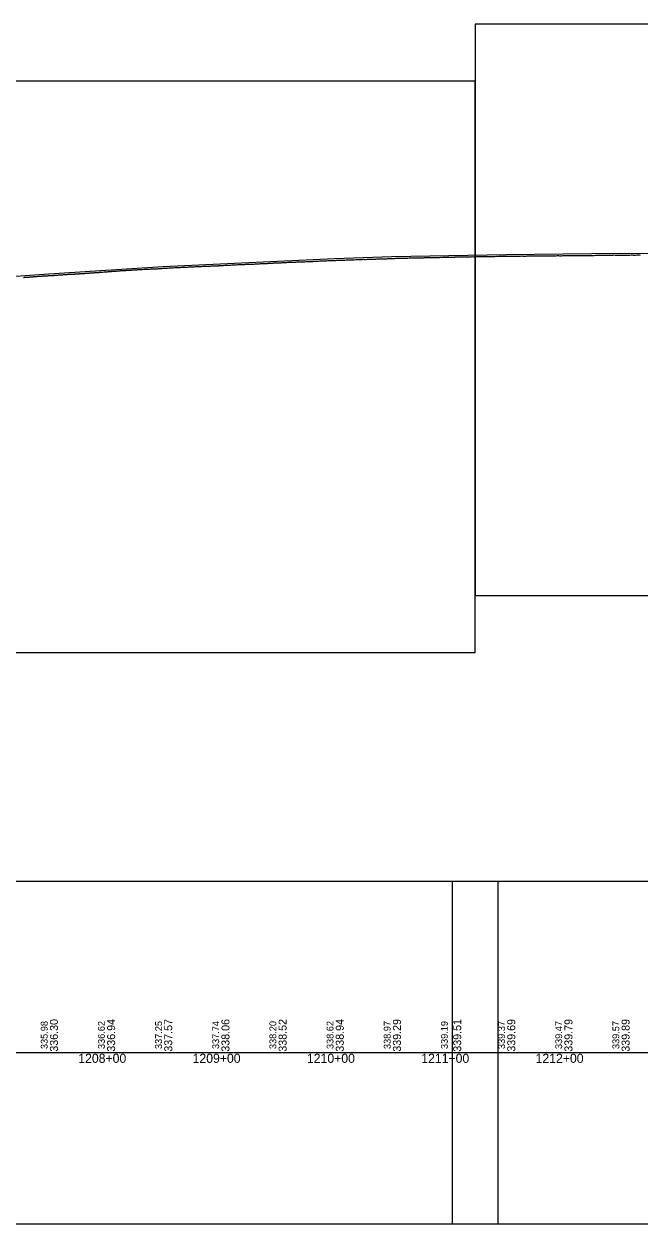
# Model space of a CAD drawing. Extents: x -3627 to 47473, y 2850 to 4350.
# Drawn here: x 8106 to 8644, y 2850 to 3900 of the extents above; entities that cross this region are included whole.
import ezdxf

# ---------------------------------------------------------------- set-up
doc = ezdxf.new("R2010")
doc.units = 0
for name, color, linetype in [('RD_DDB_Profile_EX', 7, 'Continuous'), ('RD_DDB_Profile_PR', 7, 'Continuous'), ('RD_DDB_StaTX', 7, 'Continuous'), ('RD_DDB_StripGrade', 7, 'Continuous'), ('RD_GPK_Profile_Cell', 7, 'Continuous'), ('RD_SHT_ShtClip', 7, 'Continuous')]:
    doc.layers.add(name, color=color, linetype=linetype)

msp = doc.modelspace()

# ---------------------------------------------------------------- linework, layer by layer
at = {"layer": 'RD_DDB_Profile_EX'}
for points in [[(8468.94793, 3695.81724), (8469.943036, 3695.866545), (8470.591115, 3695.818705), (8471.584155, 3695.87025), (8472.576556, 3695.86732), (8473.579379, 3695.86649), (8474.57258, 3695.865875), (8475.575565, 3695.91508), (8476.578407, 3695.96363), (8477.571559, 3695.96294), (8478.572907, 3695.958895), (8479.575681, 3695.95811), (8480.578538, 3696.006895), (8481.571496, 3696.05564), (8482.12012, 3696.109715), (8482.574301, 3696.153895), (8483.577047, 3696.15262), (8484.568784, 3696.14851), (8485.662579, 3696.14695), (8486.911776, 3696.144415), (8487.659355, 3696.14225), (8488.66334, 3696.24287), (8489.656766, 3696.24039), (8490.660179, 3696.237365), (8491.703432, 3696.23449), (8492.657639, 3696.23483), (8493.661105, 3696.281105), (8494.664573, 3696.277845), (8495.65805, 3696.324055), (8496.662094, 3696.37366), (8497.665618, 3696.419805), (8498.65915, 3696.36635), (8499.185064, 3696.363645), (8500.189303, 3696.41581), (8501.286743, 3696.469145), (8502.188107, 3696.47203), (8503.182525, 3696.47508), (8504.186972, 3696.477495), (8505.181283, 3696.47692), (8506.182221, 3696.52899), (8507.177132, 3696.58141), (8508.182012, 3696.583425), (8509.176921, 3696.585565), (8510.181801, 3696.5872), (8510.870055, 3696.5541), (8511.176718, 3696.5393), (8512.180877, 3696.58685), (8513.175815, 3696.58855), (8513.52939, 3696.590835), (8514.533886, 3696.63829), (8515.66171, 3696.639695), (8516.533417, 3696.64066), (8517.538063, 3696.68764), (8518.532887, 3696.73861), (8519.537498, 3696.685875), (8520.532367, 3696.73663), (8521.537316, 3696.7865), (8522.532096, 3696.73352), (8523.537038, 3696.783565), (8524.53203, 3696.83394), (8525.536799, 3696.83029), (8526.531932, 3696.83034), (8527.536785, 3696.82633), (8528.526075, 3696.875835), (8529.011668, 3696.926), (8530.036677, 3696.929565), (8531.012454, 3696.92819), (8532.008196, 3696.93118), (8533.013885, 3696.98334), (8534.009664, 3696.98626), (8535.005419, 3696.939025), (8536.01122, 3696.94089), (8537.007031, 3696.9929), (8538.01222, 3696.991185), (8539.008031, 3696.94339), (8539.619989, 3696.97541), (8540.003882, 3696.99521), (8541.009747, 3697.046345), (8542.005637, 3696.99797), (8543.011508, 3696.999115), (8543.57207, 3696.971855), (8544.411644, 3696.977315), (8544.731209, 3696.9982), (8545.727102, 3697.049125), (8546.723014, 3697.00005), (8547.729062, 3697.000435), (8548.72518, 3697.051065), (8549.2033, 3697.05125), (8549.731208, 3697.05126), (8550.727323, 3697.05159), (8551.402762, 3697.08361), (8551.732185, 3697.098915), (8552.728465, 3697.099285), (8553.994956, 3697.099665), (8554.730595, 3697.099275), (8555.7265, 3697.14909), (8556.732892, 3697.19852), (8557.727472, 3697.194955), (8558.786612, 3697.094875), (8559.729585, 3697.09385), (8560.727446, 3697.14313)], [(8560.727446, 3697.14313), (8561.731695, 3697.14204), (8562.730001, 3697.141325), (8563.726318, 3697.19053), (8564.882987, 3697.236155), (8565.889759, 3697.237695), (8566.886999, 3697.19329), (8567.883786, 3697.14543), (8568.369923, 3697.170815), (8568.880633, 3697.197195), (8569.514814, 3697.2), (8569.888699, 3697.20125), (8570.88626, 3697.252285), (8571.883832, 3697.303385), (8573.161579, 3697.29368), (8573.890559, 3697.25784), (8574.888014, 3697.258995), (8575.887442, 3697.26245), (8576.884935, 3697.312675), (8577.953234, 3697.36365), (8578.891382, 3697.366865), (8579.88874, 3697.36644), (8580.886129, 3697.415225), (8582.132423, 3697.41787), (8582.74489, 3697.38733), (8583.148776, 3697.37099), (8584.159097, 3697.373285), (8585.157466, 3697.425795), (8586.157831, 3697.42692), (8587.158515, 3697.37924), (8587.536546, 3697.39906), (8588.158688, 3697.43128), (8589.155629, 3697.43064), (8590.164898, 3697.480585), (8591.165186, 3697.43717), (8592.328201, 3697.47965), (8593.164677, 3697.440655), (8594.164592, 3697.442135), (8595.160884, 3697.535645), (8596.424402, 3697.54016), (8597.420888, 3697.54086), (8598.417556, 3697.54113), (8599.423269, 3697.49094), (8600.419515, 3697.48922), (8601.418806, 3697.53692), (8601.911513, 3697.560955), (8602.415023, 3697.582025), (8603.420781, 3697.53144), (8604.416901, 3697.531065), (8605.413289, 3697.587145), (8606.703168, 3697.595745), (8607.417437, 3697.62848), (8608.41359, 3697.674985), (8609.409513, 3697.720675), (8610.415135, 3697.67015), (8611.494824, 3697.721955), (8612.405101, 3697.76615), (8613.620711, 3697.76436), (8614.621041, 3697.765485), (8615.621393, 3697.76784), (8616.28648, 3697.7694), (8616.621714, 3697.77005), (8617.621971, 3697.81899), (8618.622188, 3697.869535), (8619.622443, 3697.824635), (8620.622697, 3697.829005), (8621.078136, 3697.85269), (8621.622852, 3697.879385), (8622.623012, 3697.83512), (8623.623173, 3697.83832), (8624.623333, 3697.83857), (8625.869791, 3697.799695), (8626.623853, 3697.83824), (8627.625756, 3697.847325), (8628.625764, 3697.846655), (8629.625841, 3697.84599), (8630.661447, 3697.845265), (8631.625912, 3697.841965), (8632.576806, 3697.843835), (8633.576828, 3697.802625), (8634.576849, 3697.851385), (8635.578675, 3697.852455), (8636.578593, 3697.898365), (8637.578512, 3697.898645), (8638.57843, 3697.8556), (8639.580145, 3697.85842), (8640.58003, 3697.8539), (8641.579851, 3697.901435), (8642.60486, 3697.951475), (8643.607934, 3697.903895), (8644.607849, 3697.85144)], [(8189.829123, 3684.147975), (8190.292238, 3684.19276), (8190.595755, 3684.17839), (8191.293806, 3684.246265), (8191.595796, 3684.2616), (8192.588766, 3684.293895), (8193.588782, 3684.336805), (8194.620779, 3684.42178), (8195.588801, 3684.46876), (8196.588704, 3684.54406), (8197.588676, 3684.605875), (8198.588646, 3684.661095), (8199.588564, 3684.744165), (8200.588495, 3684.778115), (8201.588424, 3684.812385), (8202.588351, 3684.88705), (8203.308945, 3684.948635), (8204.307813, 3684.9965), (8205.307013, 3685.06899), (8206.305388, 3685.116405), (8207.296257, 3685.176375), (8208.295701, 3685.212865), (8209.293926, 3685.2978), (8210.348583, 3685.39595), (8211.345577, 3685.39319), (8212.343902, 3685.377045), (8213.340846, 3685.446675), (8213.787402, 3685.467815), (8214.338974, 3685.482805), (8215.335555, 3685.567475), (8216.333514, 3685.643115), (8217.329646, 3685.649995), (8218.579057, 3685.809255), (8219.323814, 3685.854045), (8220.321399, 3685.82103), (8221.31749, 3685.85768), (8222.313538, 3685.878465), (8223.370713, 3686.052105), (8224.301282, 3686.10602), (8225.301519, 3686.15631), (8226.300221, 3686.19556), (8227.298924, 3686.25301), (8228.299123, 3686.267195), (8229.297517, 3686.297845), (8230.29591, 3686.40795), (8231.295847, 3686.490325), (8232.293923, 3686.52077), (8233.293761, 3686.553375), (8234.291859, 3686.668615), (8235.289958, 3686.67496), (8236.178328, 3686.75826), (8237.178328, 3686.797955), (8238.178329, 3686.84614), (8239.178331, 3686.90324), (8240.56958, 3687.008155), (8241.568906, 3687.06518), (8242.568227, 3687.0721), (8243.566948, 3687.12067), (8244.567617, 3687.16382), (8245.566355, 3687.1625), (8246.565392, 3687.21149), (8247.56436, 3687.303045), (8248.562822, 3687.351535), (8249.561571, 3687.400305), (8250.561677, 3687.450395), (8251.560442, 3687.470435), (8252.558822, 3687.5185), (8253.557306, 3687.566685), (8254.555799, 3687.65136), (8255.421101, 3687.69353), (8255.970195, 3687.698965), (8256.970244, 3687.755645), (8257.970129, 3687.80514), (8258.969568, 3687.877365), (8259.96946, 3687.88342), (8260.969431, 3687.89605), (8261.990175, 3687.98782), (8262.990337, 3688.075435), (8263.990629, 3688.03842), (8264.989889, 3688.043285), (8265.990181, 3688.087475), (8266.495614, 3688.138), (8266.990268, 3688.18127), (8267.989361, 3688.18585), (8268.770621, 3688.192605), (8269.770589, 3688.292485), (8270.770767, 3688.38026), (8271.28727, 3688.38097), (8271.772104, 3688.400305), (8272.771812, 3688.43736), (8273.771732, 3688.474725), (8274.771436, 3688.524375), (8275.772649, 3688.531675), (8276.078926, 3688.546815), (8276.772388, 3688.60008), (8277.771826, 3688.73685), (8278.771475, 3688.78019), (8279.271242, 3688.780395), (8280.271472, 3688.793725), (8281.271697, 3688.844555), (8282.354178, 3688.893675)], [(8282.354178, 3688.893675), (8283.354956, 3688.9006), (8284.355735, 3688.90761), (8285.356513, 3688.945585), (8285.662237, 3688.976095), (8286.346628, 3689.025425), (8287.34711, 3689.13198), (8288.347337, 3689.238335), (8289.347818, 3689.244955), (8290.453893, 3689.298915), (8291.346743, 3689.349765), (8292.346922, 3689.44974), (8293.347101, 3689.449715), (8294.345503, 3689.44782), (8295.345652, 3689.54165), (8296.345529, 3689.541295), (8297.224113, 3689.584915), (8297.722631, 3689.583335), (8298.723488, 3689.63465), (8299.724342, 3689.735955), (8300.037204, 3689.767135), (8300.724242, 3689.829105), (8301.724984, 3689.880025), (8302.724959, 3689.891655), (8303.7257, 3689.942715), (8304.82886, 3689.949945), (8305.726321, 3689.942795), (8306.726955, 3689.987285), (8307.726828, 3690.098685), (8308.727461, 3690.19324), (8309.727326, 3690.148355), (8310.727858, 3690.161125), (8311.543649, 3690.21041), (8312.540677, 3690.30696), (8313.541457, 3690.35134), (8314.543177, 3690.447045), (8315.536257, 3690.49908), (8316.536697, 3690.505745), (8317.538443, 3690.55111), (8318.540004, 3690.566515), (8319.540559, 3690.65301), (8320.541941, 3690.754375), (8321.542386, 3690.76828), (8322.543941, 3690.81305), (8323.545306, 3690.87164), (8323.995483, 3690.894135), (8324.545661, 3690.91429), (8325.555385, 3690.96532), (8326.554599, 3690.97034), (8327.553631, 3691.01784), (8328.787138, 3691.121685), (8329.553003, 3691.1447), (8330.551878, 3691.13575), (8331.550914, 3691.19022), (8332.549785, 3691.23786), (8333.578794, 3691.29332), (8334.548639, 3691.33462), (8335.547505, 3691.388045), (8336.546362, 3691.474025), (8337.545071, 3691.466045), (8338.543888, 3691.47985), (8339.350979, 3691.53887), (8340.351491, 3691.584325), (8341.350671, 3691.627975), (8342.351944, 3691.63364), (8343.351051, 3691.687575), (8344.351951, 3691.78255), (8345.353123, 3691.822525), (8346.351922, 3691.8814), (8347.352825, 3691.886625), (8348.351471, 3691.934895), (8349.352006, 3692.019735), (8350.352804, 3692.014755), (8351.351219, 3692.023), (8352.342821, 3692.07774), (8352.745417, 3692.07692), (8353.340983, 3692.08043), (8354.340225, 3692.17048), (8355.340654, 3692.220165), (8356.266749, 3692.268695), (8357.537072, 3692.3245), (8358.269563, 3692.33326), (8359.271862, 3692.379665), (8360.271864, 3692.415025), (8361.274418, 3692.47075), (8362.328728, 3692.538535), (8363.276335, 3692.58016), (8364.278217, 3692.626065), (8365.271423, 3692.63657), (8366.27104, 3692.63546), (8367.272861, 3692.67653), (8368.2721, 3692.77052), (8369.237998, 3692.821105), (8370.239529, 3692.821545), (8371.376016, 3692.921), (8371.91204, 3692.94714), (8372.376183, 3692.96515), (8373.377463, 3692.965285), (8374.37888, 3692.92963), (8375.37882, 3693.032475), (8376.370297, 3693.03757)], [(8376.370297, 3693.03757), (8376.703695, 3693.070265), (8377.370261, 3693.126575), (8378.371382, 3693.13089), (8379.372635, 3693.230895), (8380.372541, 3693.27889), (8381.495351, 3693.33452), (8382.373427, 3693.36364), (8383.374394, 3693.413185), (8384.375487, 3693.47127), (8385.365286, 3693.47319), (8386.366246, 3693.47262), (8387.36582, 3693.515975), (8388.560718, 3693.607265), (8389.561822, 3693.61044), (8390.563812, 3693.61931), (8391.078662, 3693.64465), (8391.56481, 3693.67203), (8392.556629, 3693.71353), (8393.557653, 3693.66618), (8394.55877, 3693.720695), (8395.870318, 3693.79422), (8396.583817, 3693.853825), (8397.58588, 3693.90431), (8398.586341, 3693.94957), (8399.577694, 3693.948655), (8400.661974, 3693.99418), (8401.580034, 3694.004555), (8402.5804, 3694.11303), (8403.580009, 3694.06435), (8404.300222, 3694.06084), (8405.453629, 3694.11128), (8406.294812, 3694.10807), (8407.296465, 3694.151505), (8408.29812, 3694.20461), (8409.299932, 3694.254625), (8410.291702, 3694.30783), (8411.293051, 3694.310535), (8412.294557, 3694.357005), (8413.29591, 3694.35967), (8414.297265, 3694.409165), (8415.289287, 3694.411795), (8416.290488, 3694.45797), (8417.290949, 3694.50711), (8418.292016, 3694.553285), (8419.293228, 3694.555515), (8419.828596, 3694.58186), (8420.294164, 3694.60161), (8421.285207, 3694.596075), (8421.986711, 3694.643715), (8422.988442, 3694.65348), (8423.990214, 3694.755065), (8424.620252, 3694.75272), (8424.990762, 3694.748995), (8425.992489, 3694.795055), (8426.984736, 3694.84612), (8427.98648, 3694.896885), (8428.987759, 3694.89739), (8429.411908, 3694.91783), (8429.989507, 3694.941375), (8430.990526, 3694.983455), (8431.992233, 3694.983425), (8432.983994, 3695.030095), (8434.203564, 3695.02798), (8434.987442, 3695.027815), (8435.989134, 3695.075525), (8436.990103, 3695.12103), (8437.981835, 3695.166945), (8438.995219, 3695.166635), (8439.424462, 3695.169055), (8440.426681, 3695.16948), (8441.428702, 3695.21817), (8442.421214, 3695.26631), (8443.423434, 3695.31513), (8443.786875, 3695.315), (8444.42547, 3695.31601), (8445.42731, 3695.315185), (8446.412066, 3695.315235), (8447.41528, 3695.366195), (8448.578531, 3695.413795), (8449.419944, 3695.412815), (8450.4125, 3695.462455), (8451.414898, 3695.461275), (8452.417288, 3695.410575), (8453.409713, 3695.459035), (8454.412102, 3695.50746), (8454.937228, 3695.507475), (8455.940815, 3695.55828), (8456.944291, 3695.608605), (8458.161842, 3695.611895), (8458.943396, 3695.611535), (8459.946743, 3695.661855), (8460.940369, 3695.663045), (8461.943575, 3695.714085), (8462.953498, 3695.713725), (8463.942247, 3695.717715), (8464.945389, 3695.71766), (8465.948532, 3695.718445), (8466.941827, 3695.76863), (8467.944934, 3695.76933), (8468.94793, 3695.81724)], [(8105.179761, 3678.30375), (8105.672961, 3678.32812), (8106.18004, 3678.35318), (8106.674779, 3678.377145), (8107.17968, 3678.4273), (8107.671253, 3678.451785), (8108.370976, 3678.486865), (8108.672296, 3678.50168), (8109.175646, 3678.526435), (8109.674154, 3678.55041), (8110.174962, 3678.57504), (8110.675627, 3678.64973), (8111.174934, 3678.724215), (8111.677099, 3678.74891), (8112.175563, 3678.773965), (8112.678578, 3678.79815), (8113.169876, 3678.82253), (8113.67515, 3678.847285), (8114.169574, 3678.920875), (8114.671642, 3678.97097), (8115.164158, 3678.97047), (8115.673574, 3678.99487), (8116.16381, 3678.97044), (8116.674729, 3678.995565), (8117.163485, 3679.092805), (8118.163099, 3679.215945), (8118.678254, 3679.266115), (8119.161799, 3679.289665), (8119.679856, 3679.34081), (8120.161824, 3679.364865), (8120.964195, 3679.413855), (8121.486588, 3679.46486), (8121.964419, 3679.53645), (8122.964875, 3679.635675), (8123.490158, 3679.66112), (8123.964969, 3679.63677), (8124.493709, 3679.66197), (8124.965034, 3679.68541), (8125.495639, 3679.71125), (8125.965368, 3679.734615), (8126.492281, 3679.76051), (8126.960361, 3679.87731), (8127.537599, 3679.92895), (8128.164846, 3679.954625), (8128.702754, 3679.981255), (8129.165624, 3679.981065), (8129.704354, 3680.00776), (8130.166402, 3680.00759), (8130.700606, 3680.06129), (8131.161788, 3680.01511), (8131.703531, 3680.041765), (8132.329255, 3680.164115), (8132.706384, 3680.182755), (8133.163623, 3680.18254), (8133.708326, 3680.2095), (8134.164384, 3680.25483), (8134.710268, 3680.309085), (8135.165146, 3680.3543), (8135.713559, 3680.40826), (8136.166073, 3680.453235), (8136.715504, 3680.452945), (8137.162479, 3680.49719), (8137.714315, 3680.551865)], [(8137.714315, 3680.551865), (8138.16325, 3680.551555), (8138.716626, 3680.60647), (8139.164021, 3680.58391), (8139.720317, 3680.61108), (8140.164972, 3680.699635), (8140.717101, 3680.72709), (8141.1603, 3680.77055), (8142.161055, 3680.84171), (8142.72307, 3680.869205), (8143.161808, 3680.89067), (8143.727114, 3680.917645), (8144.162732, 3680.96068), (8144.72977, 3680.960035), (8145.163616, 3680.98056), (8145.733489, 3681.065275), (8146.160073, 3681.08634), (8146.731895, 3681.14288), (8147.160847, 3681.18521), (8147.736358, 3681.21256), (8148.161808, 3681.08483), (8148.739397, 3681.11343), (8149.16272, 3681.11315), (8149.743482, 3681.112955), (8150.163495, 3681.322185), (8150.740729, 3681.379565), (8151.145799, 3681.42123), (8151.731893, 3681.448765), (8152.146691, 3681.44865), (8152.734306, 3681.447725), (8153.147527, 3681.426485), (8153.559325, 3681.426385), (8154.148212, 3681.484525), (8154.558274, 3681.566415), (8155.148898, 3681.654155), (8155.744167, 3681.682455), (8156.554248, 3681.70205), (8157.150661, 3681.731035), (8157.548788, 3681.77107), (8158.147369, 3681.830065), (8158.749575, 3681.82925), (8159.323924, 3681.84774), (8159.719371, 3681.92661), (8160.325284, 3681.985995), (8160.71857, 3682.00545), (8161.326681, 3682.065085), (8161.717158, 3682.02538), (8162.328586, 3682.08568), (8162.716113, 3682.104875), (8163.330089, 3682.134785), (8163.715062, 3682.153855), (8164.331598, 3682.21476), (8164.713557, 3682.32874), (8165.33351, 3682.35851), (8165.870845, 3682.37687), (8166.33509, 3682.375815), (8166.711232, 3682.413035), (8167.330495, 3682.474015), (8167.703185, 3682.51036), (8168.33251, 3682.540205), (8168.701843, 3682.53983), (8169.334149, 3682.569935), (8169.700493, 3682.56959), (8170.335794, 3682.63178), (8170.69869, 3682.63108), (8171.337907, 3682.661765), (8171.697092, 3682.71527), (8172.339698, 3682.745845), (8172.695486, 3682.781), (8173.341495, 3682.876335), (8173.689924, 3682.893145), (8174.340183, 3682.956795), (8174.688338, 3682.95649), (8175.686691, 3683.004905), (8176.344003, 3683.069425), (8176.684451, 3683.08586), (8177.346363, 3683.08464), (8177.682612, 3683.117905), (8178.348369, 3683.116375), (8178.680764, 3683.182375), (8179.343684, 3683.34798), (8179.671769, 3683.38003), (8180.40672, 3683.37843), (8180.730794, 3683.377945), (8181.59497, 3683.458585), (8182.275991, 3683.52547), (8182.595093, 3683.605695), (8183.277413, 3683.6383), (8183.595215, 3683.63874), (8184.278847, 3683.637315), (8184.595338, 3683.637755), (8185.281923, 3683.738045), (8185.595389, 3683.76971), (8186.283739, 3683.837005), (8186.595492, 3683.86901), (8187.284863, 3683.901925), (8187.595573, 3683.93334), (8188.288302, 3683.99971), (8188.595604, 3684.015395), (8189.290179, 3684.048545), (8189.829123, 3684.147975)]]:
    msp.add_lwpolyline(points, dxfattribs=at)
at = {"layer": 'RD_DDB_Profile_PR'}
msp.add_lwpolyline([(7877.33, 3659.958), (7927.33, 3665.0295), (7977.33, 3669.793), (8027.33, 3674.1615), (8077.33, 3677.821), (8127.33, 3681.5105), (8177.33, 3684.6845), (8227.33, 3687.8535), (8277.33, 3690.2765), (8327.33, 3692.607), (8377.33, 3694.723), (8427.33, 3696.4635), (8477.33, 3697.563), (8527.33, 3698.427), (8577.33, 3698.934), (8627.33, 3699.4445), (8677.33, 3698.842)], dxfattribs=at)
at = {"layer": 'RD_GPK_Profile_Cell'}
msp.add_line((1000, 3000), (46705.077602, 3000), dxfattribs=at)
at = {"layer": 'RD_SHT_ShtClip'}
for points in [[(10000.165, 3400), (10000.165, 3900), (10000.165, 3900), (8500.33, 3900), (8500.33, 3400)], [(8500.165, 3350), (8500.165, 3850), (8500.165, 3850), (7000.33, 3850), (7000.33, 3350)], [(6980.33, 3150), (8520, 3150), (8520, 2850), (6980.33, 2850)], [(8480.33, 3150), (10020, 3150), (10020, 2850), (8480.33, 2850)]]:
    msp.add_lwpolyline(points, close=True, dxfattribs=at)

# ---------------------------------------------------------------- texts
at = {"layer": 'RD_DDB_StaTX'}
for s, p in [('1208+00', (8153.125471, 2991)), ('1209+00', (8253.125471, 2991)), ('1210+00', (8353.125471, 2991)), ('1211+00', (8453.125471, 2991)), ('1212+00', (8553.125471, 2991))]:
    msp.add_text(s, height=8, dxfattribs=at).set_placement(p)
at = {"layer": 'RD_DDB_StripGrade'}
for s, height, p in [('335.98', 6, (8126.33, 3003.073688)), ('336.30', 7, (8135.33, 3000.75)), ('336.62', 6, (8176.33, 3003.073688)), ('336.94', 7, (8185.33, 3000.75)), ('337.25', 6, (8226.33, 3003.073688)), ('337.57', 7, (8235.33, 3000.75)), ('337.74', 6, (8276.33, 3003.073688)), ('338.06', 7, (8285.33, 3000.75)), ('338.20', 6, (8326.33, 3003.073688)), ('338.52', 7, (8335.33, 3000.75)), ('338.62', 6, (8376.33, 3003.073688)), ('338.94', 7, (8385.33, 3000.75)), ('338.97', 6, (8426.33, 3003.073688)), ('339.29', 7, (8435.33, 3000.75)), ('339.19', 6, (8476.33, 3003.073688)), ('339.51', 7, (8488.046873, 3000.75)), ('339.37', 6, (8526.33, 3003.073688)), ('339.69', 7, (8535.33, 3000.75)), ('339.47', 6, (8576.33, 3003.073688)), ('339.79', 7, (8585.33, 3000.75)), ('339.57', 6, (8626.33, 3003.073688)), ('339.89', 7, (8635.33, 3000.75))]:
    msp.add_text(s, height=height, rotation=90, dxfattribs=at).set_placement(p)

doc.saveas('drawing.dxf')
